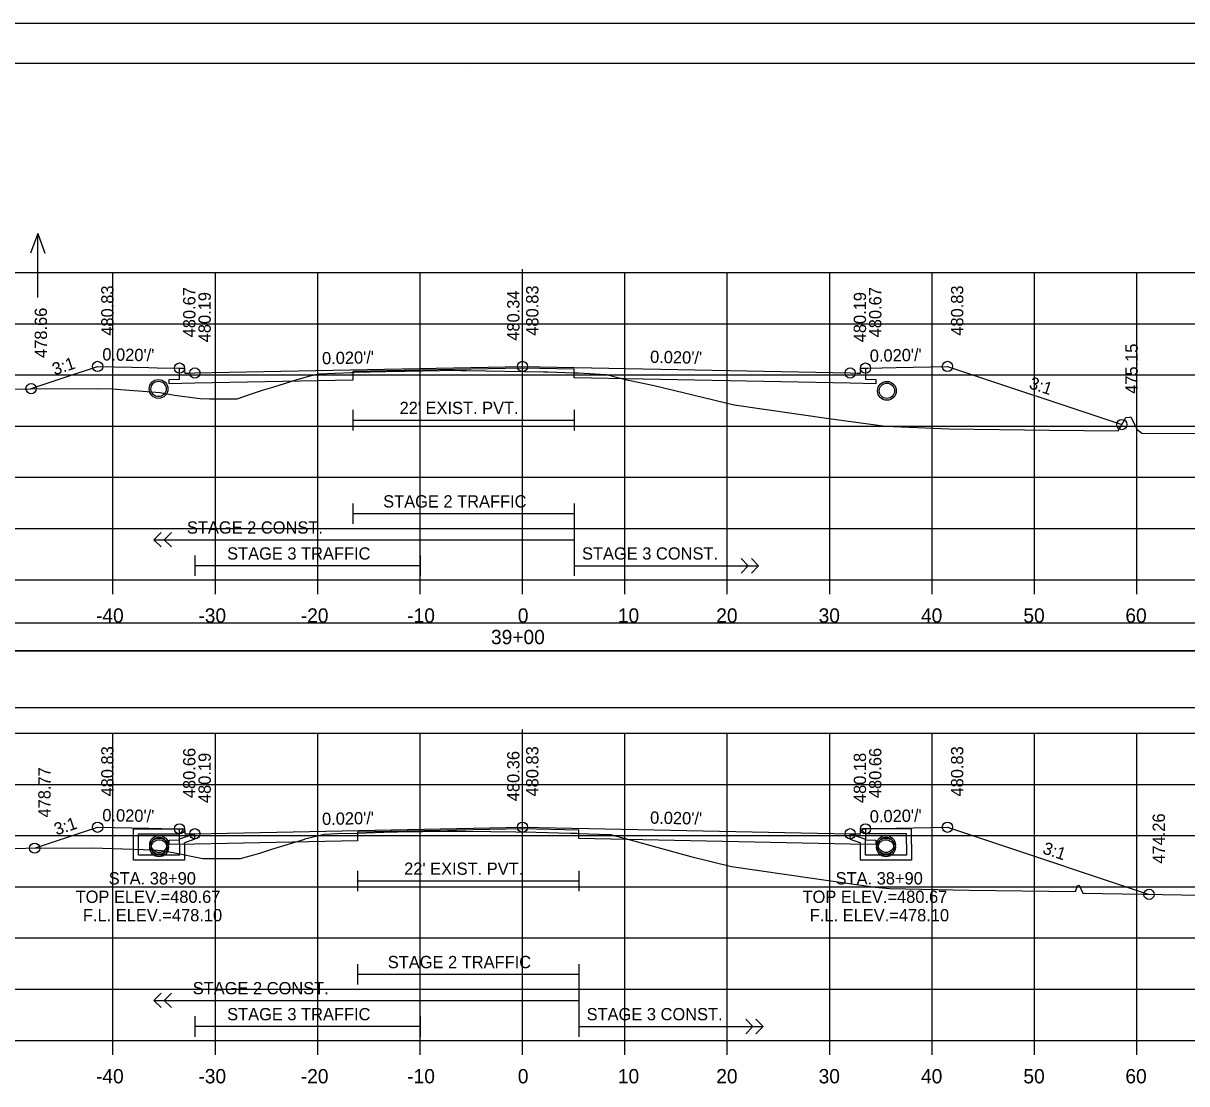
# Model space of a CAD drawing. Extents: x 1371057 to 1372761, y 380005 to 390517.
# Drawn here: x 1371845.4 to 1371959.1, y 381394.9 to 381498.4 of the extents above; entities that cross this region are included whole.
import ezdxf

# ---------------------------------------------------------------- set-up
doc = ezdxf.new("R2010")
doc.units = 0
for name, color, linetype in [('R_Alt Surface', 7, 'Continuous'), ('R_Axis', 7, 'Continuous'), ('R_Axis Annot', 7, 'Continuous'), ('R_Border', 7, 'Continuous'), ('R_Detour', 7, 'Continuous'), ('R_Dimension', 7, 'Continuous'), ('R_Exist Surface', 7, 'Continuous'), ('R_Fin Surface', 7, 'Continuous'), ('R_Grid', 7, 'Continuous'), ('R_No Plot', 7, 'Continuous'), ('R_Striping', 7, 'Continuous'), ('R_Water', 7, 'Continuous'), ('R_Water Annot', 7, 'Continuous'), ('R_Xsect Elev', 7, 'Continuous'), ('R_Xsect Slope', 7, 'Continuous')]:
    doc.layers.add(name, color=color, linetype=linetype)

msp = doc.modelspace()

# ---------------------------------------------------------------- linework, layer by layer
at = {"layer": 'R_Alt Surface'}
for points in [[(1371927.71, 381464.76), (1371927.71, 381463.68), (1371928.71, 381463.66), (1371928.71, 381463.23), (1371926.21, 381463.28), (1371899.26, 381463.81), (1371899.26, 381464.64), (1371894.21, 381464.75), (1371877.63, 381464.41), (1371877.63, 381463.58), (1371862.21, 381463.28), (1371859.71, 381463.23), (1371859.71, 381463.66), (1371860.71, 381463.68), (1371860.71, 381464.76)], [(1371877.63, 381460.67), (1371877.63, 381458.67)], [(1371899.26, 381460.67), (1371899.26, 381458.67)], [(1371877.63, 381459.67), (1371899.26, 381459.67)], [(1371927.71, 381419.75), (1371927.71, 381418.67), (1371928.71, 381418.65), (1371928.71, 381418.22), (1371926.21, 381418.27), (1371899.71, 381418.8), (1371899.71, 381419.63), (1371894.21, 381419.74), (1371878.08, 381419.42), (1371878.08, 381418.59), (1371862.21, 381418.27), (1371859.71, 381418.22), (1371859.71, 381418.65), (1371860.71, 381418.67), (1371860.71, 381419.75)], [(1371878.08, 381415.66), (1371878.08, 381413.66)], [(1371878.08, 381414.66), (1371899.71, 381414.66)], [(1371899.71, 381415.66), (1371899.71, 381413.66)]]:
    msp.add_lwpolyline(points, dxfattribs=at)
at = {"layer": 'R_Axis'}
for p, q in [((1371744.21, 381444.09), (1372044.21, 381444.09)), ((1371854.21, 381442.69), (1371854.21, 381444.09)), ((1371864.21, 381442.69), (1371864.21, 381444.09)), ((1371874.21, 381442.69), (1371874.21, 381444.09)), ((1371884.21, 381442.69), (1371884.21, 381444.09)), ((1371894.21, 381442.69), (1371894.21, 381444.09)), ((1371904.21, 381442.69), (1371904.21, 381444.09)), ((1371914.21, 381442.69), (1371914.21, 381444.09)), ((1371924.21, 381442.69), (1371924.21, 381444.09)), ((1371934.21, 381442.69), (1371934.21, 381444.09)), ((1371944.21, 381442.69), (1371944.21, 381444.09)), ((1371954.21, 381442.69), (1371954.21, 381444.09)), ((1371744.21, 381399.09), (1372044.21, 381399.09)), ((1371854.21, 381397.69), (1371854.21, 381399.09)), ((1371864.21, 381397.69), (1371864.21, 381399.09)), ((1371874.21, 381397.69), (1371874.21, 381399.09)), ((1371884.21, 381397.69), (1371884.21, 381399.09)), ((1371894.21, 381397.69), (1371894.21, 381399.09)), ((1371904.21, 381397.69), (1371904.21, 381399.09)), ((1371914.21, 381397.69), (1371914.21, 381399.09)), ((1371924.21, 381397.69), (1371924.21, 381399.09)), ((1371934.21, 381397.69), (1371934.21, 381399.09)), ((1371944.21, 381397.69), (1371944.21, 381399.09)), ((1371954.21, 381397.69), (1371954.21, 381399.09))]:
    msp.add_line(p, q, dxfattribs=at)
at = {"layer": 'R_Border'}
for p, q in [((1371736.21, 381494.55), (1372052.39, 381494.55)), ((1371888.73, 381494.29), (1371888.73, 381494.29)), ((1371888.73, 381494.29), (1371888.73, 381494.29))]:
    msp.add_line(p, q, dxfattribs=at)
at = {"layer": 'R_Detour'}
msp.add_lwpolyline([(1371741.06, 381437.13), (1372047.37, 381437.13), (1372047.37, 381439.84), (1371741.06, 381439.84)], close=True, dxfattribs=at)
at = {"layer": 'R_Dimension'}
msp.add_lwpolyline([(1371741.06, 381431.61), (1372047.37, 381431.61), (1372047.37, 381437.13), (1371741.06, 381437.13)], close=True, dxfattribs=at)
at = {"layer": 'R_Exist Surface'}
for points in [[(1371820.4, 381462.6), (1371852.57, 381462.78), (1371854.13, 381462.74), (1371858.81, 381462.37), (1371860.21, 381462.12), (1371862.71, 381461.78), (1371863.64, 381461.77), (1371866.34, 381461.75), (1371867.75, 381462.24), (1371868.9, 381462.62), (1371869.83, 381462.91), (1371872.21, 381463.66), (1371873.46, 381463.99), (1371874.31, 381464.2), (1371877.5, 381464.34), (1371877.63, 381464.34), (1371877.8, 381464.35), (1371882.35, 381464.45), (1371882.76, 381464.46), (1371887.83, 381464.54), (1371888.2, 381464.53), (1371888.23, 381464.53), (1371888.23, 381464.53), (1371888.74, 381464.52), (1371896.25, 381464.39), (1371896.71, 381464.38), (1371899.24, 381464.3), (1371899.26, 381464.3), (1371899.69, 381464.28), (1371902.38, 381464.14), (1371904.41, 381463.62), (1371904.74, 381463.54), (1371907.06, 381463.05), (1371914.88, 381461.16), (1371924.12, 381459.83), (1371929.65, 381459.07), (1371935.88, 381458.81), (1371945.67, 381458.69), (1371952.39, 381458.63), (1371952.58, 381458.94), (1371953.15, 381459.94), (1371953.48, 381459.97), (1371953.62, 381460), (1371954.22, 381458.8), (1371954.7, 381458.4), (1371966.01, 381458.34)], [(1371839.12, 381417.82), (1371852.2, 381417.89), (1371858.12, 381417.71), (1371858.96, 381417.65), (1371860.08, 381417.45), (1371862.97, 381416.86), (1371865.46, 381416.85), (1371866.67, 381416.86), (1371868.55, 381417.38), (1371869.74, 381417.78), (1371872.94, 381418.75), (1371872.95, 381418.76), (1371872.95, 381418.76), (1371874.85, 381419.23), (1371876.14, 381419.29), (1371878.08, 381419.34), (1371880.67, 381419.42), (1371881.99, 381419.45), (1371886.87, 381419.52), (1371888.27, 381419.54), (1371888.37, 381419.54), (1371888.67, 381419.53), (1371888.67, 381419.53), (1371893.55, 381419.46), (1371895.5, 381419.42), (1371898.9, 381419.34), (1371899.53, 381419.32), (1371899.71, 381419.31), (1371902.68, 381419.2), (1371902.84, 381419.19), (1371903.03, 381419.14), (1371905.08, 381418.59), (1371910.65, 381417.04), (1371914.62, 381416.08), (1371922.51, 381414.94), (1371928.66, 381414.05), (1371930.08, 381413.92), (1371937.82, 381413.77), (1371948.21, 381413.62), (1371948.42, 381414.23), (1371948.57, 381414.26), (1371948.95, 381413.48), (1371958.61, 381413.29), (1371965.22, 381413.25)]]:
    msp.add_lwpolyline(points, dxfattribs=at)
at = {"layer": 'R_Fin Surface'}
for points in [[(1371846.21, 381462.75), (1371846.21, 381462.75), (1371849.45, 381463.83), (1371852.71, 381464.92), (1371857.71, 381464.82), (1371858.54, 381464.8), (1371860.71, 381464.76), (1371861.01, 381464.76), (1371861.21, 381464.76), (1371861.21, 381464.52), (1371861.22, 381464.26), (1371861.63, 381464.26), (1371862.21, 381464.28), (1371862.21, 381464.28), (1371894.21, 381464.92), (1371894.21, 381464.92), (1371926.21, 381464.28), (1371926.88, 381464.26), (1371927.21, 381464.26), (1371927.21, 381464.38), (1371927.21, 381464.76), (1371927.66, 381464.76), (1371927.71, 381464.76), (1371927.96, 381464.76), (1371930.71, 381464.82), (1371935.71, 381464.92), (1371952.75, 381459.24)], [(1371846.56, 381417.86), (1371846.83, 381417.95), (1371852.71, 381419.91), (1371857.71, 381419.81), (1371860.29, 381419.76), (1371860.71, 381419.75), (1371860.8, 381419.75), (1371861.21, 381419.75), (1371861.22, 381419.41), (1371861.22, 381419.25), (1371861.62, 381419.26), (1371862.21, 381419.27), (1371894.21, 381419.91), (1371894.21, 381419.91), (1371905.48, 381419.69), (1371926.21, 381419.27), (1371927.21, 381419.25), (1371927.21, 381419.55), (1371927.21, 381419.75), (1371927.38, 381419.75), (1371927.71, 381419.75), (1371930.1, 381419.8), (1371930.71, 381419.81), (1371935.71, 381419.91), (1371939.03, 381418.81), (1371955.4, 381413.35)]]:
    msp.add_lwpolyline(points, dxfattribs=at)
at = {"layer": 'R_Grid'}
for p, q in [((1371744.21, 381474.09), (1372044.21, 381474.09)), ((1371854.21, 381444.09), (1371854.21, 381474.09)), ((1371864.21, 381444.09), (1371864.21, 381474.09)), ((1371874.21, 381444.09), (1371874.21, 381474.09)), ((1371884.21, 381444.09), (1371884.21, 381474.09)), ((1371894.21, 381444.09), (1371894.21, 381474.09)), ((1371904.21, 381444.09), (1371904.21, 381474.09)), ((1371914.21, 381444.09), (1371914.21, 381474.09)), ((1371924.21, 381444.09), (1371924.21, 381474.09)), ((1371934.21, 381444.09), (1371934.21, 381474.09)), ((1371944.21, 381444.09), (1371944.21, 381474.09)), ((1371954.21, 381444.09), (1371954.21, 381474.09)), ((1371744.21, 381469.09), (1372044.21, 381469.09)), ((1371744.21, 381464.09), (1372044.21, 381464.09)), ((1371744.21, 381459.09), (1372044.21, 381459.09)), ((1371744.21, 381454.09), (1372044.21, 381454.09)), ((1371744.21, 381449.09), (1372044.21, 381449.09)), ((1371744.21, 381444.09), (1372044.21, 381444.09)), ((1371744.21, 381429.09), (1372044.21, 381429.09)), ((1371854.21, 381399.09), (1371854.21, 381429.09)), ((1371864.21, 381399.09), (1371864.21, 381429.09)), ((1371874.21, 381399.09), (1371874.21, 381429.09)), ((1371884.21, 381399.09), (1371884.21, 381429.09)), ((1371894.21, 381399.09), (1371894.21, 381429.09)), ((1371904.21, 381399.09), (1371904.21, 381429.09)), ((1371914.21, 381399.09), (1371914.21, 381429.09)), ((1371924.21, 381399.09), (1371924.21, 381429.09)), ((1371934.21, 381399.09), (1371934.21, 381429.09)), ((1371944.21, 381399.09), (1371944.21, 381429.09)), ((1371954.21, 381399.09), (1371954.21, 381429.09)), ((1371744.21, 381424.09), (1372044.21, 381424.09)), ((1371744.21, 381419.09), (1372044.21, 381419.09)), ((1371744.21, 381414.09), (1372044.21, 381414.09)), ((1371744.21, 381409.09), (1372044.21, 381409.09)), ((1371744.21, 381404.09), (1372044.21, 381404.09)), ((1371744.21, 381399.09), (1372044.21, 381399.09))]:
    msp.add_line(p, q, dxfattribs=at)
at = {"layer": 'R_No Plot'}
msp.add_line((1371723.81, 381498.44), (1372057.14, 381498.44), dxfattribs=at)
for points in [[(1371723.8, 381498.44), (1372057.14, 381498.44), (1372057.14, 381285.1), (1371723.8, 381285.1)], [(1371970.13, 381494.55), (1371989.75, 381494.55), (1371989.75, 381484.67), (1372005.86, 381484.67), (1372029.06, 381484.67), (1372029.18, 381456.51), (1372052.39, 381456.51), (1372052.39, 381289.09), (1371736.21, 381289.09), (1371736.21, 381494.55)]]:
    msp.add_lwpolyline(points, close=True, dxfattribs=at)
for centre, radius in [((1371852.71, 381464.92), 0.5), ((1371860.71, 381464.76), 0.5), ((1371862.21, 381464.28), 0.5), ((1371894.21, 381464.92), 0.5), ((1371926.21, 381464.28), 0.5), ((1371927.71, 381464.76), 0.5), ((1371935.71, 381464.92), 0.5), ((1371858.66, 381462.72), 0.917), ((1371846.21, 381462.75), 0.5), ((1371929.8, 381462.54), 0.917), ((1371952.75, 381459.24), 0.5), ((1371852.71, 381419.91), 0.5), ((1371894.21, 381419.91), 0.5), ((1371935.71, 381419.91), 0.5), ((1371860.71, 381419.75), 0.5), ((1371862.21, 381419.27), 0.5), ((1371926.21, 381419.27), 0.5), ((1371927.71, 381419.75), 0.5), ((1371846.56, 381417.86), 0.5), ((1371858.71, 381418.19), 0.917), ((1371858.71, 381417.94), 0.917), ((1371929.71, 381418.19), 0.917), ((1371929.71, 381417.94), 0.917), ((1371955.4, 381413.35), 0.5)]:
    msp.add_circle(centre, radius, dxfattribs=at)
at = {"layer": 'R_Striping'}
for p, q in [((1371877.63, 381451.54), (1371877.63, 381449.54)), ((1371899.26, 381451.54), (1371899.26, 381444.45)), ((1371877.63, 381450.54), (1371899.26, 381450.54)), ((1371858.21, 381447.99), (1371858.91, 381448.7)), ((1371858.21, 381447.99), (1371899.26, 381447.99)), ((1371858.91, 381447.29), (1371858.21, 381447.99)), ((1371859.21, 381447.99), (1371859.91, 381448.7)), ((1371859.91, 381447.29), (1371859.21, 381447.99)), ((1371862.21, 381446.45), (1371862.21, 381444.45)), ((1371884.21, 381445.45), (1371862.21, 381445.45)), ((1371884.21, 381446.45), (1371884.21, 381444.45)), ((1371899.26, 381445.45), (1371917.26, 381445.45)), ((1371899.3, 381445.45), (1371909.3, 381445.45)), ((1371916.26, 381445.45), (1371915.56, 381446.16)), ((1371915.56, 381444.74), (1371916.26, 381445.45)), ((1371917.26, 381445.45), (1371916.56, 381446.16)), ((1371916.56, 381444.74), (1371917.26, 381445.45)), ((1371878.08, 381406.54), (1371878.08, 381404.54)), ((1371899.71, 381406.54), (1371899.71, 381399.45)), ((1371878.08, 381405.54), (1371899.71, 381405.54)), ((1371858.21, 381402.99), (1371858.91, 381403.7)), ((1371859.21, 381402.99), (1371859.91, 381403.7)), ((1371858.21, 381402.99), (1371899.71, 381402.99)), ((1371858.91, 381402.29), (1371858.21, 381402.99)), ((1371859.91, 381402.29), (1371859.21, 381402.99)), ((1371862.21, 381401.45), (1371862.21, 381399.45)), ((1371884.21, 381401.45), (1371884.21, 381399.45)), ((1371916.71, 381400.45), (1371916.01, 381401.16)), ((1371917.71, 381400.45), (1371917.01, 381401.16)), ((1371884.21, 381400.45), (1371862.21, 381400.45)), ((1371899.71, 381400.45), (1371917.71, 381400.45)), ((1371899.75, 381400.45), (1371909.75, 381400.45)), ((1371916.01, 381399.74), (1371916.71, 381400.45)), ((1371917.01, 381399.74), (1371917.71, 381400.45))]:
    msp.add_line(p, q, dxfattribs=at)
at = {"layer": 'R_Water'}
for p, q in [((1371856.21, 381419.75), (1371860.96, 381419.75)), ((1371856.21, 381418.25), (1371856.21, 381419.75)), ((1371856.71, 381418.25), (1371856.71, 381419.25)), ((1371856.71, 381419.25), (1371860.71, 381419.25)), ((1371861.04, 381419.59), (1371860.71, 381419.25)), ((1371862.21, 381419.27), (1371860.71, 381418.75)), ((1371861.04, 381419.59), (1371860.96, 381419.75)), ((1371926.21, 381419.27), (1371927.71, 381418.75)), ((1371927.38, 381419.59), (1371927.46, 381419.75)), ((1371927.38, 381419.59), (1371927.71, 381419.25)), ((1371932.21, 381419.75), (1371927.46, 381419.75)), ((1371931.71, 381419.25), (1371927.71, 381419.25)), ((1371931.71, 381418.25), (1371931.71, 381419.25)), ((1371932.21, 381418.25), (1371932.21, 381419.75)), ((1371860.71, 381418.25), (1371860.71, 381418.75)), ((1371862.21, 381418.74), (1371861.21, 381418.4)), ((1371861.21, 381418.25), (1371861.21, 381418.4)), ((1371926.21, 381418.74), (1371927.21, 381418.4)), ((1371927.21, 381418.25), (1371927.21, 381418.4)), ((1371927.71, 381418.25), (1371927.71, 381418.75))]:
    msp.add_line(p, q, dxfattribs=at)
for points in [[(1371862.21, 381418.74), (1371862.21, 381419.27)], [(1371926.21, 381418.74), (1371926.21, 381419.27)], [(1371861.21, 381418.25), (1371861.21, 381416.69), (1371858.71, 381416.69), (1371856.21, 381416.69), (1371856.21, 381418.25)], [(1371860.71, 381418.25), (1371860.71, 381417.19), (1371858.71, 381417.19), (1371856.71, 381417.19), (1371856.71, 381418.25)], [(1371932.21, 381418.25), (1371932.21, 381416.69), (1371929.71, 381416.69), (1371927.21, 381416.69), (1371927.21, 381418.25)], [(1371931.71, 381418.25), (1371931.71, 381417.19), (1371929.71, 381417.19), (1371927.71, 381417.19), (1371927.71, 381418.25)]]:
    msp.add_lwpolyline(points, dxfattribs=at)
for centre in [(1371858.66, 381462.72), (1371929.8, 381462.54), (1371858.71, 381418.19), (1371858.71, 381417.94), (1371929.71, 381418.19), (1371929.71, 381417.94)]:
    msp.add_circle(centre, 0.75, dxfattribs=at)
at = {"layer": 'R_Water Annot'}
for p, q in [((1371846.86, 381477.92), (1371846.16, 381476)), ((1371846.86, 381471.64), (1371846.86, 381477.92)), ((1371846.86, 381477.92), (1371847.56, 381476))]:
    msp.add_line(p, q, dxfattribs=at)
at = {"layer": 'R_Xsect Elev'}
for p, q in [((1371894.21, 381464.43), (1371894.21, 381474.43)), ((1371894.21, 381419.45), (1371894.21, 381429.45))]:
    msp.add_line(p, q, dxfattribs=at)

# ---------------------------------------------------------------- texts
at = {"layer": 'R_Axis Annot'}
for s, p in [('-40', (1371852.55, 381439.89)), ('-30', (1371862.55, 381439.89)), ('-20', (1371872.55, 381439.89)), ('-10', (1371882.95, 381439.89)), ('0', (1371893.75, 381439.89)), ('10', (1371903.52, 381439.89)), ('20', (1371913.13, 381439.89)), ('30', (1371923.13, 381439.89)), ('40', (1371933.13, 381439.89)), ('50', (1371943.13, 381439.89)), ('60', (1371953.09, 381439.89)), ('39+00', (1371891.13, 381437.79)), ('-40', (1371852.55, 381394.89)), ('-30', (1371862.55, 381394.89)), ('-20', (1371872.55, 381394.89)), ('-10', (1371882.95, 381394.89)), ('0', (1371893.75, 381394.89)), ('10', (1371903.52, 381394.89)), ('20', (1371913.13, 381394.89)), ('30', (1371923.13, 381394.89)), ('40', (1371933.13, 381394.89)), ('50', (1371943.13, 381394.89)), ('60', (1371953.09, 381394.89))]:
    msp.add_text(s, height=1.4, dxfattribs=at).set_placement(p)
at = {"layer": 'R_Striping'}
for s, p in [('STAGE 2 TRAFFIC', (1371880.6, 381451.14)), ('STAGE 2 CONST.', (1371861.43, 381448.59)), ('STAGE 3 TRAFFIC', (1371865.36, 381446.05)), ('STAGE 3 CONST.', (1371900.02, 381446.05)), ('STAGE 2 TRAFFIC', (1371881.05, 381406.14)), ('STAGE 2 CONST.', (1371862, 381403.59)), ('STAGE 3 TRAFFIC', (1371865.36, 381401.05)), ('STAGE 3 CONST.', (1371900.47, 381401.05))]:
    msp.add_text(s, height=1.2, dxfattribs=at).set_placement(p)
at = {"layer": 'R_Water'}
for p in [(1371882.2, 381460.27), (1371882.65, 381415.26)]:
    msp.add_text("22' EXIST. PVT.", height=1.2, dxfattribs=at).set_placement(p)
at = {"layer": 'R_Water Annot'}
for s, p in [('STA. 38+90', (1371853.79, 381414.32)), ('STA. 38+90', (1371924.79, 381414.32)), ('TOP ELEV.=480.67', (1371850.56, 381412.52)), ('TOP ELEV.=480.67', (1371921.56, 381412.52)), ('F.L. ELEV.=478.10', (1371851.27, 381410.72)), ('F.L. ELEV.=478.10', (1371922.27, 381410.72))]:
    msp.add_text(s, height=1.2, dxfattribs=at).set_placement(p)
at = {"layer": 'R_Xsect Elev'}
for s, p in [('480.83', (1371854.26, 381467.92)), ('480.83', (1371895.76, 381467.92)), ('480.83', (1371937.26, 381467.92)), ('480.67', (1371862.26, 381467.76)), ('480.19', (1371863.76, 381467.28)), ('480.34', (1371893.91, 381467.43)), ('480.19', (1371927.76, 381467.28)), ('480.67', (1371929.26, 381467.76)), ('478.66', (1371847.76, 381465.75)), ('475.15', (1371954.3, 381462.24)), ('480.83', (1371854.26, 381422.91)), ('480.66', (1371862.26, 381422.75)), ('480.36', (1371893.91, 381422.45)), ('480.83', (1371895.76, 381422.91)), ('480.66', (1371929.26, 381422.75)), ('480.83', (1371937.26, 381422.91)), ('480.19', (1371863.76, 381422.27)), ('480.18', (1371927.76, 381422.27)), ('478.77', (1371848.11, 381420.86)), ('474.26', (1371956.95, 381416.35))]:
    msp.add_text(s, height=1.2, rotation=90, dxfattribs=at).set_placement(p)
at = {"layer": 'R_Xsect Slope'}
for s, rotation, p in [('3:1', 18.4325, (1371848.51, 381464.04)), ("0.020'/'", 358.8542, (1371853.16, 381465.51)), ("0.020'/'", 1.1457, (1371874.64, 381465.12)), ("0.020'/'", 358.8543, (1371906.66, 381465.27)), ("0.020'/'", 1.1457, (1371928.14, 381465.36)), ('3:1', 341.5673, (1371943.6, 381462.81)), ("0.020'/'", 358.8543, (1371853.16, 381420.5)), ("0.020'/'", 1.1457, (1371874.64, 381420.12)), ("0.020'/'", 358.8542, (1371906.66, 381420.26)), ("0.020'/'", 1.1458, (1371928.14, 381420.36)), ('3:1', 18.4345, (1371848.69, 381419.1)), ('3:1', 341.5643, (1371944.93, 381417.37))]:
    msp.add_text(s, height=1.2, rotation=rotation, dxfattribs=at).set_placement(p)

doc.saveas('drawing.dxf')
